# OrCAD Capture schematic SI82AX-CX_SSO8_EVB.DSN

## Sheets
1 PAGE3_Power_Connectors: size A; title: Power Connectors; rev: 1.0; note: SI82AX-CX_SSO8_EVB
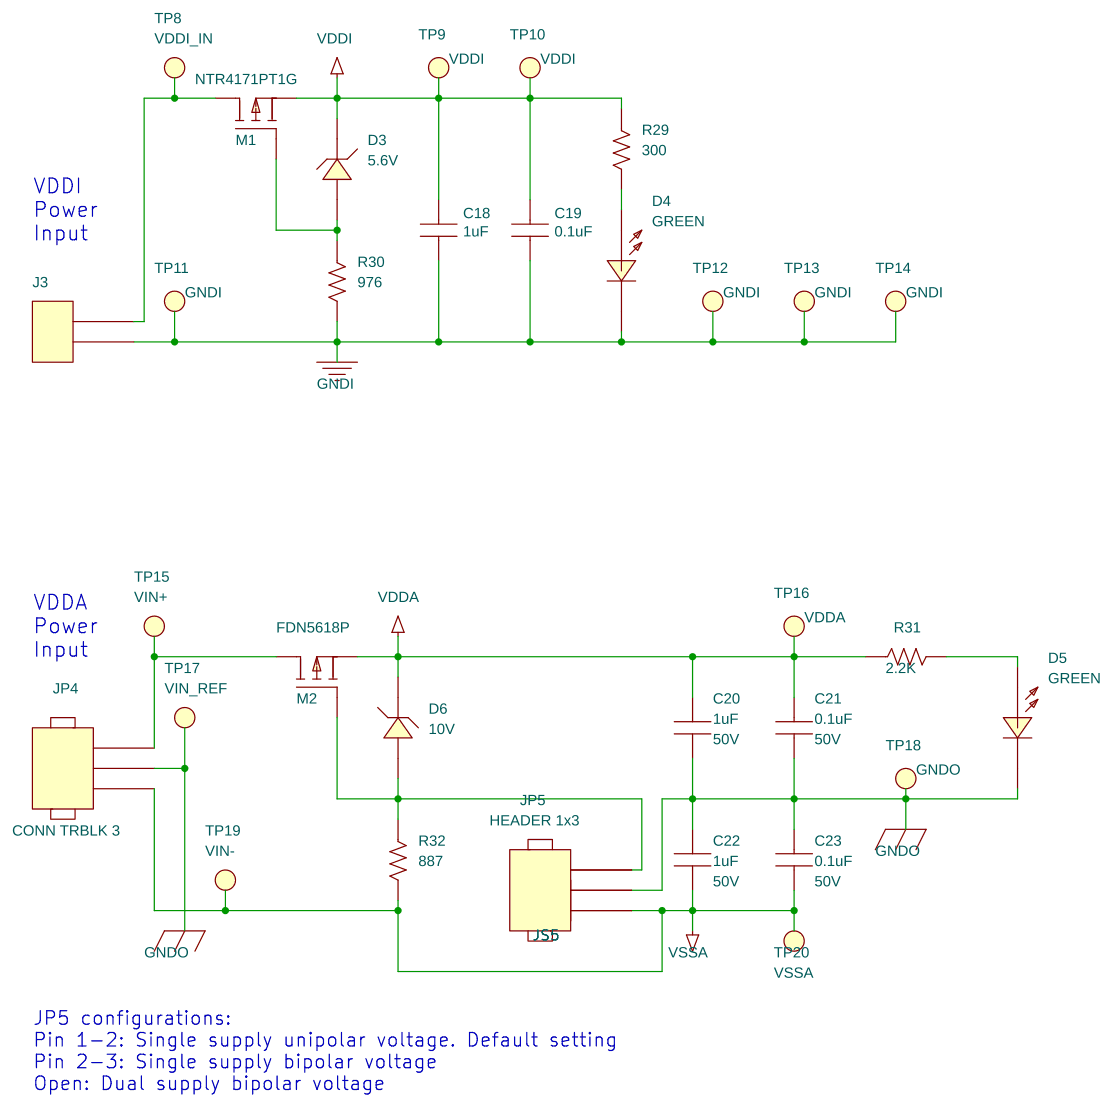
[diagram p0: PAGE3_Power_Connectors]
2 PAGE2_Mechanicals: size A; title: Mechanicals
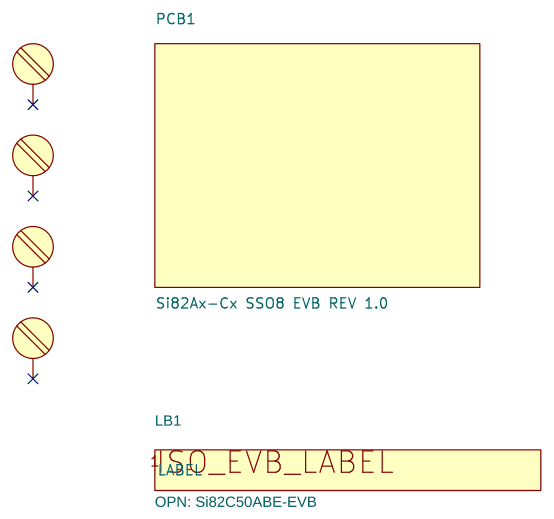
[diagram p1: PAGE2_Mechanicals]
3 PAGE1_Single_Driver: size B; title: Single Driver
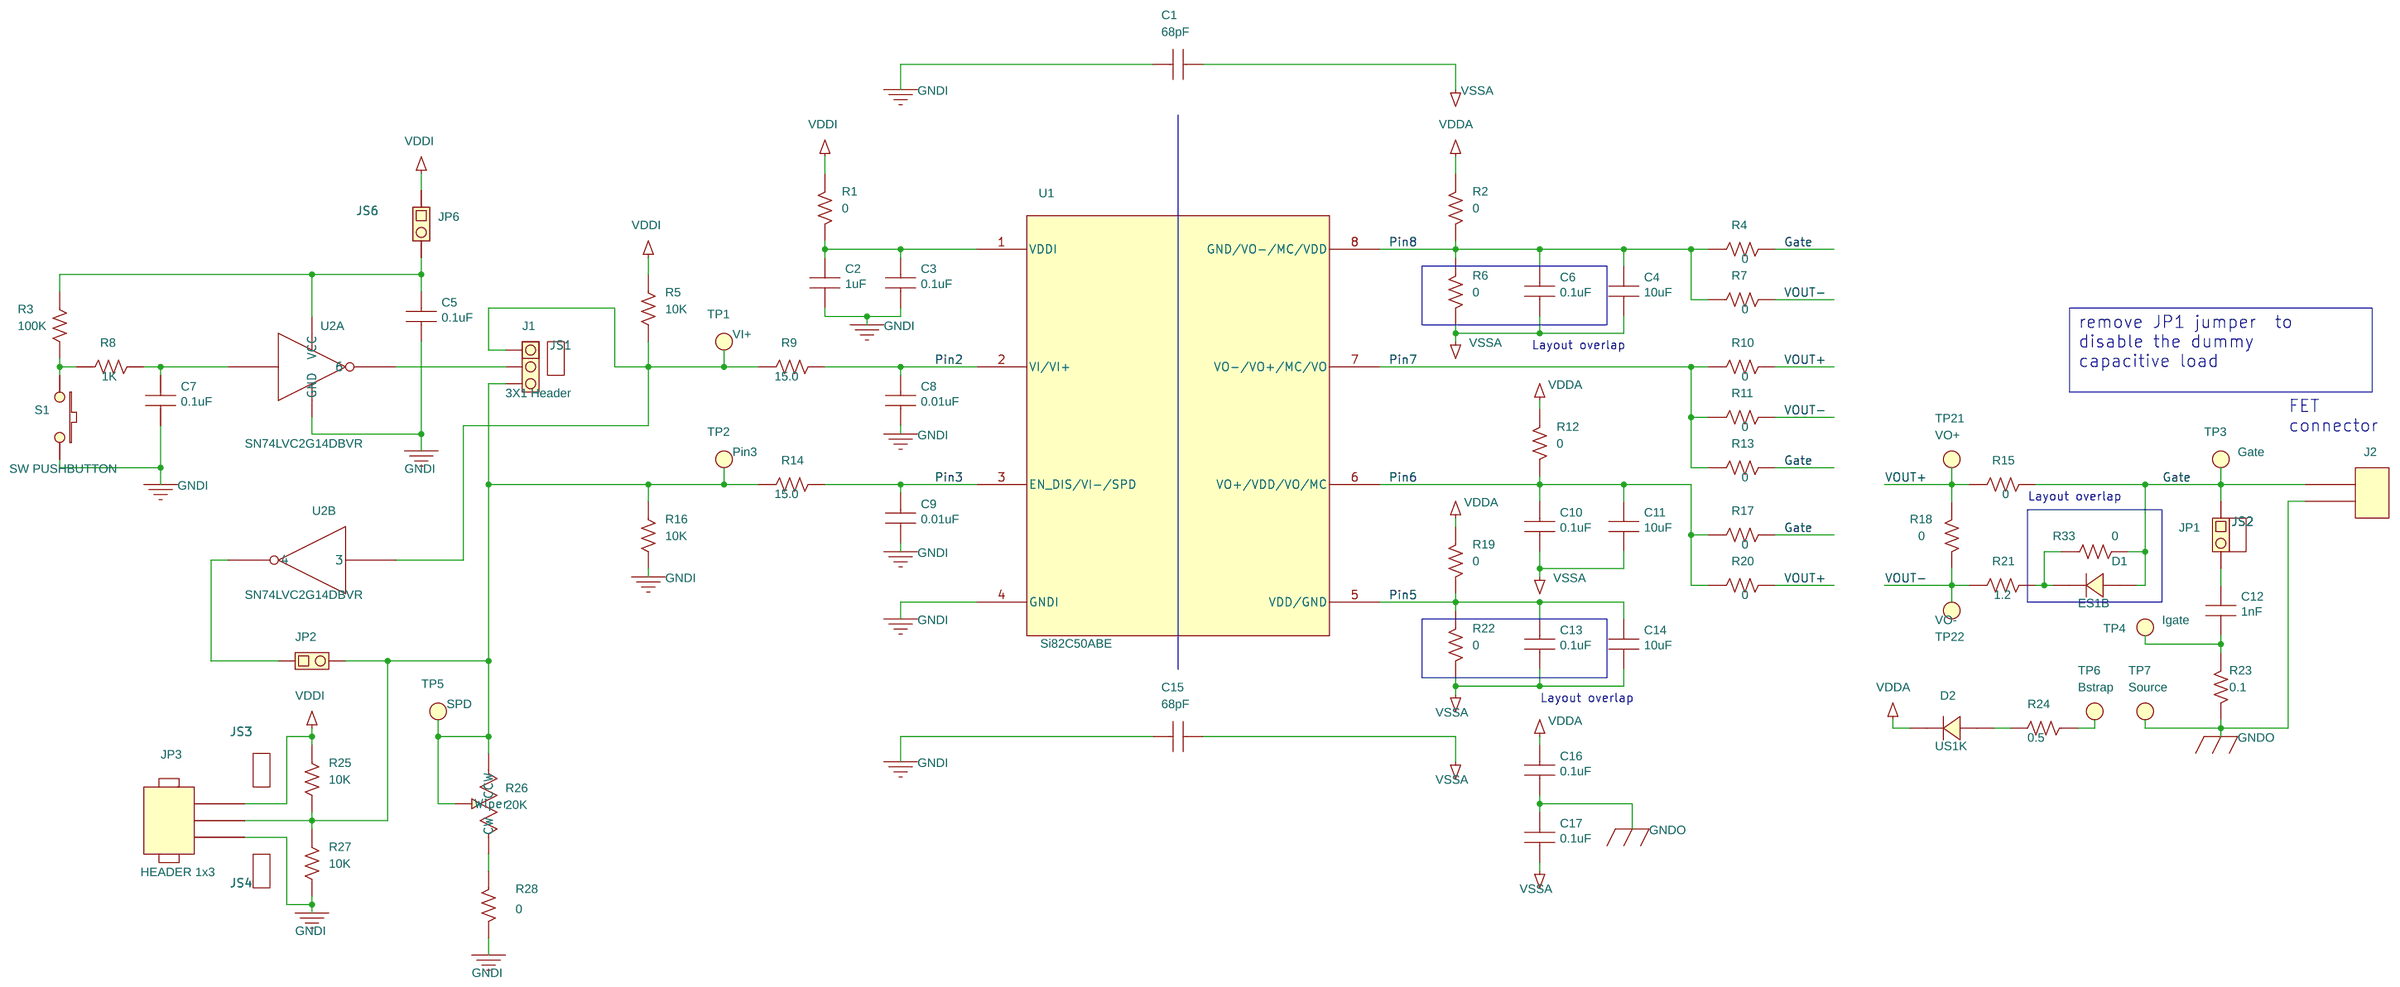
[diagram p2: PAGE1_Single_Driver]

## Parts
sheet PAGE1_Single_Driver
C1  68pF  [C1808]
C2  1uF  [C0603]
C3  0.1uF  [C0603]
C4  10uF  [C0805]
C5  0.1uF  [C0603]
C6  0.1uF  [C0603]
C7  0.1uF  [C0603]
C8  0.01uF  [C0402]
C9  0.01uF  [C0402]
C10  0.1uF  [C0603]
C11  10uF  [C0805]
C12  1nF  [C0805]
C13  0.1uF  [C0603]
C14  10uF  [C0805]
C15  68pF  [C1808]
C16  0.1uF  [C0603]
C17  0.1uF  [C0603]
D1  ES1B  [DO-214AC]
D2  US1K  [DO-214AC]
J1  3X1 Header  [CONN1X3-TSM]
J2  CONN TRBLK 2  [CON1X2-1725656]
JP1  HEADER 1X2  [CONN1X2]
JP2  HEADER 1X2  [CONN1X2]
JP3  HEADER 1x3  [CONN-1X3]
JP6  HEADER 1X2  [CONN1X2]
JS1  Jumper Shunt  [SHUNT]
JS2  Jumper Shunt  [SHUNT]
JS3  Jumper Shunt  [SHUNT]
JS4  Jumper Shunt  [SHUNT]
JS6  Jumper Shunt  [SHUNT]
R1  0  [R0603]
R2  0  [R0603]
R3  100K  [R0603]
R4  0  [R0805]
R5  10K  [R0603]
R6  0  [R0603]
R7  0  [R0805]
R8  1K  [R0603]
R9  15.0  [R0603]
R10  0  [R0805]
R11  0  [R0805]
R12  0  [R0603]
R13  0  [R0805]
R14  15.0  [R0603]
R15  0  [R0805]
R16  10K  [R0603]
R17  0  [R0805]
R18  0  [R0603]
R19  0  [R0603]
R20  0  [R0805]
R21  1.2  [R0805]
R22  0  [R0603]
R23  0.1  [R0603]
R24  0.5  [R0805]
R25  10K  [R0603]
R26  20K  [POT-PVG3A]
R27  10K  [R0603]
R28  0  [R0603]
R33  0  [R0805]
S1  SW PUSHBUTTON  [SW-PB-TL3302]
TP1  TESTPOINT  [TP_MINIATURE_SMT]
TP2  TESTPOINT  [TP_MINIATURE_SMT]
TP3  TESTPOINT  [TP_MINIATURE_SMT]
TP4  TESTPOINT  [TP_MINIATURE_SMT]
TP5  TESTPOINT  [TP_MINIATURE_SMT]
TP6  TESTPOINT  [TP_MINIATURE_SMT]
TP7  TESTPOINT  [TP_MINIATURE_SMT]
TP21  TESTPOINT  [TP_MINIATURE_SMT]
TP22  TESTPOINT  [TP_MINIATURE_SMT]
U1  Si82C50ABE  [SO8N11.5P1.27]
U2  SN74LVC2G14DBVR  [SOT6N2.8P0.95]  (sections A,B)
sheet PAGE2_Mechanicals
LB1  OPN: Si82C50ABE-EVB  [PTL-14-717]
MH1  SCREW/STANDOFF  [MH-125]
MH2  SCREW/STANDOFF  [MH-125]
MH3  SCREW/STANDOFF  [MH-125]
MH4  SCREW/STANDOFF  [MH-125]
PCB1  Si82Ax-Cx SSO8 EVB REV 1.0  [N/A]
sheet PAGE3_Power_Connectors
C18  1uF  [C0603]
C19  0.1uF  [C0402]
C20  1uF  [C0805]
C21  0.1uF  [C0603]
C22  1uF  [C0805]
C23  0.1uF  [C0603]
D3  5.6V  [SOD-123]
D4  GREEN  [LED-0603]
D5  GREEN  [LED-0603]
D6  10V  [SOD-123]
J3  CONN TRBLK 2  [CON1X2-1725656]
JP4  CONN TRBLK 3  [CON1X3-1725669]
JP5  HEADER 1x3  [CONN-1X3]
JS5  Jumper Shunt  [SHUNT]
M1  NTR4171PT1G  [SOT23-GSD]
M2  FDN5618P  [SOT23-GSD]
R29  300  [R0603]
R30  976  [R1206]
R31  2.2K  [R1206]
R32  887  [R2512]
TP8  RED  [TESTPOINT]
TP9  TESTPOINT  [TP_MINIATURE_SMT]
TP10  TESTPOINT  [TP_MINIATURE_SMT]
TP11  BLACK  [TESTPOINT]
TP12  TESTPOINT  [TP_MINIATURE_SMT]
TP13  TESTPOINT  [TP_MINIATURE_SMT]
TP14  TESTPOINT  [TP_MINIATURE_SMT]
TP15  RED  [TESTPOINT]
TP16  TESTPOINT  [TP_MINIATURE_SMT]
TP17  BLACK  [TESTPOINT]
TP18  TESTPOINT  [TP_MINIATURE_SMT]
TP19  WHITE  [TESTPOINT]
TP20  TESTPOINT  [TP_MINIATURE_SMT]

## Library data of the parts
C1 C15 = CAP_NP: CAP, 68pF, 250V, ±10%, Y2, 1808; Manufacturer: MuRata; ManufacturerPN: GA342D1XGF680JY02L; Rating: Y2; SiLabsPN: GA342D1XGF680JY02L; Tolerance: ±10%; Type: Y2; Voltage: 250V; Datasheet: muRata Safety Y1-3.pdf
C2 = CAP_NP: CAP, 1uF, 25V, ±10%, X7R, 0603; FPLIST: C0603,C0603L; Manufacturer: MuRata; ManufacturerPN: GCM188R71E105KA49; SiLabsPN: GCM188R71E105KA49; Tolerance: ±10%; Type: X7R; Voltage: 25V; Datasheet: GCM188R71E105KA49_EC-data.pdf
C3 C5 C7 = CAP_NP: CAP, 0.1uF, 25V, ±10%, X7R, 0603; Manufacturer: Venkel; ManufacturerPN: C0603X7R250-104K; SiLabsPN: C0603X7R250-104K; Tolerance: ±10%; Type: X7R; Voltage: 25V; Datasheet: PID_C.pdf
C4 C11 C14 = CAP_NP: CAP, 10uF, 50V, ±10%, X5R, 0805; Manufacturer: Murata; ManufacturerPN: GRM21BR61H106KE43L; SiLabsPN: C0805X5R500-106K; Tolerance: ±10%; Type: X5R; Voltage: 50V; Datasheet: GRM21BR61H106KE43-01A.pdf
C6 C10 C13 C16 C17 C21 C23 = CAP_NP: CAP, 0.1uF, 50V, ±10%, X7R, 0603; Manufacturer: Venkel; ManufacturerPN: C0603X7R500-104K; SiLabsPN: C0603X7R500-104K; Tolerance: ±10%; Type: X7R; Voltage: 50V; Datasheet: PID_C.pdf
C8 C9 = CAP_NP: CAP, 0.01uF, 25V, ±10%, X7R, 0402; Manufacturer: Venkel; ManufacturerPN: C0402X7R250-103K; SiLabsPN: C0402X7R250-103K; Tolerance: ±10%; Type: X7R; Voltage: 25V; Datasheet: PID_C.pdf
C12 = CAP_NP: CAP, 1nF, 50V, ±1%, C0G, 0805; Manufacturer: Venkel; ManufacturerPN: C0805C0G500-102F; SiLabsPN: C0805C0G500-102F; Tolerance: ±1%; Type: C0G; Voltage: 50V; Datasheet: PID_C.pdf
D1 = DIODE: DIO, FAST, 100V, 1.0A, SMA; Manufacturer: Diodes Inc.; Rating: 1.0A; Type: Fast; Voltage: 100V; Datasheet: ds14001.pdf
D2 = DIODE: DIO, SWITCH, ULTRA FAST, 800V, 1.0A, SMA; Manufacturer: Diodes Inc.; ManufacturerPN: US1K-13-F; Rating: 1.0A; SiLabsPN: US1K-13-F; Type: Switch, Ultra Fast; Voltage: 800V; Datasheet: ds16008.pdf
J1 = BRCM-HDR1X3: Header, 3x1, 0.1in pitch, 10u Au Plated, SMD; Manufacturer: Samtec; ManufacturerPN: TSM-103-01-L-SV; SiLabsPN: TSM-103-01-L-SV; Type: Header; Datasheet: TSM.PDF
J2 J3 = CONN_TRBLK_2: CONN, TERM BLOCK 2POS, 2.54MM, RT PCB; Manufacturer: PHOENIX CONTACT; ManufacturerPN: 1725656; SiLabsPN: 1725656; Type: TERM BLK; Datasheet: 1725656.pdf
JP1 JP2 JP6 = JUMPER: Header, 2x1, 0.1in pitch, Tin Plated; Manufacturer: Samtec; ManufacturerPN: TSW-102-07-T-S; SiLabsPN: TSW-102-07-T-S; Type: Header; Datasheet: TSW_TH.pdf
JP3 JP5 = CONN_HEADER_3: Header, 3x1, 0.1in pitch, Tin Plated; Manufacturer: Samtec; ManufacturerPN: TSW-103-07-T-S; SiLabsPN: TSW-103-07-T-S; Type: Header; Datasheet: TSW_TH.PDF
JS1-JS6 = JMPR_SHUNT1: Shunt, 1x2, 0.1in pitch, Tin plating; Manufacturer: Samtec; ManufacturerPN: SNT-100-BK-T; SiLabsPN: SNT-100-BK-T; Type: Shunt; Datasheet: SNT.pdf
R1 R2 R6 R12 R18 R19 R22 R28 = RES: RES, 0 Ohm, 1A, ThickFilm, 0603; FPLIST: R0603,R0603L; Manufacturer: Venkel; ManufacturerPN: CR0603-16W-000; Rating: 1A; SiLabsPN: CR0603-16W-000; Type: ThickFilm; Datasheet: PID_CR.pdf
R3 = RES: RES, 100K, 1/10W, ±5%, ThickFilm, 0603; Manufacturer: Venkel; ManufacturerPN: CR0603-10W-104J; Rating: 1/10W; SiLabsPN: CR0603-10W-104J; Tolerance: ±5%; Type: ThickFilm; Datasheet: PID_CR.pdf
R4 R7 R10 R11 R13 R15 R17 R20 R33 = RES: RES, 0 Ohm, 2A, ThickFilm, 0805; Manufacturer: Venkel; ManufacturerPN: CR0805-10W-000; Rating: 2A; SiLabsPN: CR0805-10W-000; Type: ThickFilm; Datasheet: PID_CR.pdf
R5 R16 R25 R27 = RES: RES, 10K, 1/16W, ±1%, ThickFilm, 0603; Manufacturer: Venkel; ManufacturerPN: CR0603-16W-1002F; Rating: 1/16W; SiLabsPN: CR0603-16W-1002F; Tolerance: ±1%; Type: ThickFilm; Datasheet: PID_CR.pdf
R8 = RES: RES, 1K, 1/10W, ±5%, ThickFilm, 0603; Manufacturer: Venkel; ManufacturerPN: CR0603-10W-1001J; Rating: 1/10W; SiLabsPN: CR0603-10W-1001J; Tolerance: ±5%; Type: ThickFilm; Datasheet: PID_CR.pdf
R9 R14 = RES: RES, 15.0 Ohm, 1/16W, ±1%, ThickFilm, 0603; Manufacturer: Venkel; ManufacturerPN: CR0603-16W-15R0F; Rating: 1/16W; SiLabsPN: CR0603-16W-15R0F; Tolerance: ±1%; Type: ThickFilm; Datasheet: PID_CR.pdf
R21 = RES: RES, 1.2 Ohm, 1/10W, ±5%, ThickFilm, 0805; Manufacturer: Venkel; ManufacturerPN: CR0805-10W-1R2J; Rating: 1/10W; SiLabsPN: CR0805-10W-1R2J; Tolerance: ±5%; Type: ThickFilm; Datasheet: PID_CR.pdf
R23 = RES: RES, 0.1 Ohm, 1/8W, ±1%, ThickFilm, 0603; Manufacturer: Venkel; ManufacturerPN: LCR0603-R100F; Rating: 1/8W; SiLabsPN: CR0603-8W-R100F; Tolerance: ±1%; Type: ThickFilm; Datasheet: PID_CR.pdf
R24 = RES: RES, 0.5 Ohm, 1/4W, ±1%, ThickFilm, 0805; Manufacturer: Venkel; ManufacturerPN: LCR0805-R500F; Rating: 1/4W; SiLabsPN: LCR0805-R500F; Tolerance: ±1%; Type: ThickFilm; Voltage: 500V; Datasheet: PID_CR.pdf
R26 = POT: TRIMPOT, 20K, 1T, TOP ADJ, Sealed, 3mm, PVG3 Series, SMD; Manufacturer: MuRata; ManufacturerPN: PVG3A203C01R00; Rating: 1/4W; SiLabsPN: PVG3A203C01R00; Tolerance: 20%; Type: TRIM; Datasheet: PVG3 Series.pdf
S1 = SW-PB-SPST-SHORT: SWITCH, MOM, PB, TACTILE, NO, 70C, 3.5x6mm, SMD; Manufacturer: E-SWITCH; ManufacturerPN: TL3302AF180QJ; Rating: 50mA; SiLabsPN: TL3302AF180QJ; Type: Tactile; Voltage: 12VDC; Datasheet: TL3302-346326.pdf
TP1 = TEST_POINT: TESTPOINT, MINIATURE, SMD; Manufacturer: Keystone; ManufacturerPN: 5019; SiLabsPN: 5019; Silk: VI+; Datasheet: 5019.pdf
TP2 = TEST_POINT: TESTPOINT, MINIATURE, SMD; Manufacturer: Keystone; ManufacturerPN: 5019; SiLabsPN: 5019; Silk: Pin3; Datasheet: 5019.pdf
TP3 = TEST_POINT: TESTPOINT, MINIATURE, SMD; Manufacturer: Keystone; ManufacturerPN: 5019; SiLabsPN: 5019; Silk: Gate; Datasheet: 5019.pdf
TP4 = TEST_POINT: TESTPOINT, MINIATURE, SMD; Manufacturer: Keystone; ManufacturerPN: 5019; SiLabsPN: 5019; Silk: Igate; Datasheet: 5019.pdf
TP5 = TEST_POINT: TESTPOINT, MINIATURE, SMD; Manufacturer: Keystone; ManufacturerPN: 5019; SiLabsPN: 5019; Silk: SPD; Datasheet: 5019.pdf
TP6 = TEST_POINT: TESTPOINT, MINIATURE, SMD; Manufacturer: Keystone; ManufacturerPN: 5019; SiLabsPN: 5019; Silk: Bstrap; Datasheet: 5019.pdf
TP7 = TEST_POINT: TESTPOINT, MINIATURE, SMD; Manufacturer: Keystone; ManufacturerPN: 5019; SiLabsPN: 5019; Silk: Source; Datasheet: 5019.pdf
TP21 = TEST_POINT: TESTPOINT, MINIATURE, SMD; Manufacturer: Keystone; ManufacturerPN: 5019; SiLabsPN: 5019; Silk: VO+; Datasheet: 5019.pdf
TP22 = TEST_POINT: TESTPOINT, MINIATURE, SMD; Manufacturer: Keystone; ManufacturerPN: 5019; SiLabsPN: 5019; Silk: VO-; Datasheet: 5019.pdf
U1 = Si82AxBxCx_SSO8_Common: IC, ISOdriver, Performance Driver, 8V UVLO, 6KV, SO8WB; Manufacturer: Skyworks; ManufacturerPN: Si82C50ABE-IS4; Rating: 6000 VRMS; SiLabsPN: Si82C50ABE-IS4; Type: ISOdriver; Voltage: 30V; Datasheet: POD-003791_PACKAGE_OUTLINE_SOIC_8L_WB_RevA.pdf
U2 = SN74LVC2G14DBVR: IC, INVERTER DUAL SHMT-T SOT-23-6; Manufacturer: TI; ManufacturerPN: SN74LVC2G14DBV; SiLabsPN: SN74LVC2G14DBV; Type: Inverter; Voltage: 5V; Datasheet: SN74LVC2G14.pdf
LB1 = ISO_EVB_Label: LABEL, PDB, POLYIMIDE, WHITE, 1.00 in. X 0.187 in., FONT 2; Manufacturer: Skyworks; ManufacturerPN: LABEL-Si82C50ABE-EVB; SiLabsPN: LABEL-Si82C50ABE-EVB; Type: POLYIMIDE, WHITE; Datasheet: Brady TLS2200 Label PTL-14-717.pdf
MH1-MH4 = #4_PTH_SCREW-STANDOFF: SCREW/STANDOFF, 4-40X1/4" NYL, 4-40X1/4"X1" NYL, PTH; Manufacturer: VARIOUS; ManufacturerPN: NSS-4-4-01/2401; SiLabsPN: NSS-4-4-01/2401; Type: HDW; Datasheet: RichcoPlasticCo_Screws - SPC_Technology_spacers.pdf
PCB1 = PCB: PCB, BARE BOARD, Si82Ax-Cx SSO8 EVB REV 1.0; Manufacturer: Skyworks; Type: BARE PCB
C18 = CAP_NP: CAP, 1uF, 10V, ±10%, X7R, 0603; Manufacturer: Venkel; ManufacturerPN: C0603X7R100-105K; SiLabsPN: C0603X7R100-105K; Tolerance: ±10%; Type: X7R; Voltage: 10V; Datasheet: PID_C.pdf
C19 = CAP_NP: CAP, 0.1uF, 10V, ±10%, X7R, 0402; FPLIST: C0402,C0402L; Manufacturer: Venkel; ManufacturerPN: C0402X7R100-104K; SiLabsPN: C0402X7R100-104K; Tolerance: ±10%; Type: X7R; Voltage: 10V; Datasheet: PID_C.pdf
C20 C22 = CAP_NP: CAP, 1uF, 50V, ±10%, X7R, 0805; Manufacturer: Samsung; ManufacturerPN: CL21B105KBFNNNE; SiLabsPN: C0805X7R500-105K; Tolerance: ±10%; Type: X7R; Voltage: 50V; Datasheet: CL21B105KBFNNNE.pdf
D3 = DIODE_ZENER: DIO, ZENER, 5.6V, 500mW, SOD123; Manufacturer: On Semi; ManufacturerPN: SZMMSZ5232BT1G; Rating: 500mW; SiLabsPN: SZMMSZ5232BT1G; Tolerance: 5%; Type: Zener; Datasheet: MMSZ5221BT1-D.pdf
D4 D5 = LED: LED, GREEN, 528nM, 5mA, 2.8V, 154mcd, 0603; Manufacturer: LITE-ON TECHNOLOGY CORP; ManufacturerPN: LTST-C193TGKT-5A; Rating: 20mA; SiLabsPN: LTST-C193TGKT-5A; Datasheet: LTST-C193TGKT-5A.pdf
D6 = DIODE_ZENER: DIO, ZENER, 10V, 500mW, SOD123; Manufacturer: On Semi; ManufacturerPN: MMSZ4697T1G; Rating: 500mW; SiLabsPN: MMSZ4697T1G; Tolerance: 5%; Type: Zener; Datasheet: MMSZ4678T1-D.pdf
JP4 = CONN_HEADER_3: CONN, TERM BLOCK 3POS, 2.54MM, RT PCB; Manufacturer: PHOENIX CONTACT; ManufacturerPN: 1725669; SiLabsPN: 1725669; Type: TERM BLK; Datasheet: 1725669.pdf
M1 = PFET_3PIN: TRANSISTOR, MOSFET, P-CHNL, -30V, -3.5A, SOT23; Manufacturer: ON Semiconductor; Rating: -3.5A; Type: P-CHNL; Voltage: -30V; Datasheet: NTR4171P-D.PDF
M2 = PFET_3PIN: TRANSISTOR, MOSFET, P-CHNL, 60V, 1.25A, 0.3 Ohms, SOT23; Manufacturer: Fairchild; Rating: 1.25A; Type: P-CHNL; Voltage: 60V; Datasheet: FDN5618P.PDF
R29 = RES: RES, 300 Ohm, 1/16W, ±5%, ThickFilm, 0603; FPLIST: R0603,R0603L; Manufacturer: Venkel; ManufacturerPN: CR0603-16W-301J; Rating: 1/16W; SiLabsPN: CR0603-16W-301J; Tolerance: ±5%; Type: ThickFilm; Datasheet: PID_CR.pdf
R30 = RES: RES, 976 Ohm, 1/4W, ±1%, ThickFilm, 1206; Manufacturer: Venkel; ManufacturerPN: CR1206-4W-9760F; Rating: 1/4W; SiLabsPN: CR1206-4W-9760F; Tolerance: ±1%; Type: ThickFilm; Datasheet: PID_CR.pdf
R31 = RES: RES, 2.2K, 1/4W, ±5%, ThickFilm, 1206; Manufacturer: Venkel; ManufacturerPN: CR1206-4W-222JT; Rating: 1/4W; SiLabsPN: CR1206-4W-222J; Tolerance: ±5%; Type: ThickFilm; Datasheet: PID_CR.pdf
R32 = RES: RES, 887 Ohm, 1W, ±1%, ThickFilm, 2512; Manufacturer: Panasonic Electronic Components; ManufacturerPN: ERJ-1TNF8870U; Rating: 1W; SiLabsPN: CR2512-1W-8870F; Tolerance: ±1%; Type: ThickFilm; Datasheet: AOA0000C304.pdf
TP8 = TEST_POINT: TESTPOINT, RED, PTH; Manufacturer: Kobiconn; ManufacturerPN: 151-207-RC; SiLabsPN: 151-207; Silk: VDDI_IN; Type: Loop; Datasheet: KC-300780.pdf
TP9 TP10 = TEST_POINT: TESTPOINT, MINIATURE, SMD; Manufacturer: Keystone; ManufacturerPN: 5019; SiLabsPN: 5019; Silk: VDDI; Datasheet: 5019.pdf
TP11 = TEST_POINT: TESTPOINT, BLACK, PTH; Manufacturer: Kobiconn; ManufacturerPN: 151-203-RC; SiLabsPN: 151-203; Silk: GNDI; Type: Loop; Datasheet: KC-300780.pdf
TP12-TP14 = TEST_POINT: TESTPOINT, MINIATURE, SMD; Manufacturer: Keystone; ManufacturerPN: 5019; SiLabsPN: 5019; Silk: GNDI; Datasheet: 5019.pdf
TP15 = TEST_POINT: TESTPOINT, RED, PTH; Manufacturer: Kobiconn; ManufacturerPN: 151-207-RC; SiLabsPN: 151-207; Silk: VIN+; Type: Loop; Datasheet: KC-300780.pdf
TP16 = TEST_POINT: TESTPOINT, MINIATURE, SMD; Manufacturer: Keystone; ManufacturerPN: 5019; SiLabsPN: 5019; Silk: VDDA; Datasheet: 5019.pdf
TP17 = TEST_POINT: TESTPOINT, BLACK, PTH; Manufacturer: Kobiconn; ManufacturerPN: 151-203-RC; SiLabsPN: 151-203; Silk: VIN_REF; Type: Loop; Datasheet: KC-300780.pdf
TP18 = TEST_POINT: TESTPOINT, MINIATURE, SMD; Manufacturer: Keystone; ManufacturerPN: 5019; SiLabsPN: 5019; Silk: GNDO; Datasheet: 5019.pdf
TP19 = TEST_POINT: TESTPOINT, WHITE, PTH; Manufacturer: Kobiconn; ManufacturerPN: 151-201-RC; SiLabsPN: 151-201; Silk: VIN-; Type: Loop; Datasheet: KC-300780.pdf
TP20 = TEST_POINT: TESTPOINT, MINIATURE, SMD; Manufacturer: Keystone; ManufacturerPN: 5019; SiLabsPN: 5019; Silk: VSSA; Datasheet: 5019.pdf

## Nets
GNDI: C1.1 C2.2 C3.2 C5.2 C7.2 C8.2 C9.2 C15.1 C18.2 C19.2 D4.K(CATHODE) J3.2 JP3.3 R16.2 R27.2 R28.2 R30.2 S1.2 TP11.1(Point) TP12.1(Point) TP13.1(Point) TP14.1(Point) U1.4(GNDI) U2.2(GND)
GNDO: C16.2 C17.1 C20.2 C21.2 C22.1 C23.1 D5.K(CATHODE) J2.1 JP4.2 JP5.2 R23.2 TP7.1(Point) TP17.1(Point) TP18.1(Point)
VDDA: C16.1 C20.1 C21.1 D2.K(CATHODE) D6.K(CATHODE) M2.S(SOURCE) R2.1 R12.1 R19.1 R31.1 TP16.1(Point)
VDDI: C18.1 C19.1 D3.K(CATHODE) JP3.1 JP6.1 M1.S(SOURCE) R1.1 R5.1 R25.1 R29.1 TP9.1(Point) TP10.1(Point)
VSSA: C1.2 C4.2 C6.2 C10.2 C11.2 C13.2 C14.2 C15.2 C17.2 C22.2 C23.2 JP4.3 JP5.1 R6.2 R22.2 R32.2 TP19.1(Point) TP20.1(Point)
Gate: D1.A(ANODE) J2.2 JP1.1 R4.2 R13.2 R15.2 R17.2 R33.2 TP3.1(Point)
LABEL: LB1.1(LABEL)
Pin2: C8.1 R9.2 U1.2(VI/VI+)
Pin3: C9.1 R14.2 U1.3(EN_DIS/VI-/SPD)
Pin5: C13.1 C14.1 R19.2 R22.1 U1.5(VDD/GND)
Pin6: C10.1 C11.1 R12.2 R17.1 R20.1 U1.6(VO+/VDD/VO/MC)
Pin7: R10.1 R11.1 R13.1 U1.7(VO-/VO+/MC/VO)
Pin8: C4.1 C6.1 R2.2 R4.1 R6.1 R7.1 U1.8(GND/VO-/MC/VDD)
VOUT+: R10.2 R15.1 R18.1 R20.2 TP21.1(Point)
VOUT-: R7.2 R11.2 R18.2 R21.1 TP22.1(Point)
N16361749: D3.A(ANODE) M1.G(GATE) R30.1
N16362266: J3.1 M1.D(DRAIN) TP8.1(Point)
N16362479: D4.A(ANODE) R29.2
N16363374: D6.A(ANODE) JP5.3 M2.G(GATE) R32.1
N16363786: JP4.1 M2.D(DRAIN) TP15.1(Point)
N16364430: D5.A(ANODE) R31.2
N16365952: C2.1 C3.1 R1.2 U1.1(VDDI)
N16366694: J1.3 JP2.2 JP3.2 R14.1 R16.1 R25.2 R26.1(CCW) R26.2(Wiper) R27.1 TP2.1(Point) TP5.1(Point)
N16367392: R26.3(CW) R28.1
N16368114: C5.1 JP6.2 R3.1 U2.5(VCC)
N16368658: C7.1 R8.2 U2.1
N16368673: R3.2 R8.1 S1.1
N16368830: J1.2 U2.6
N16369034: J1.1 R5.2 R9.1 TP1.1(Point) U2.3
N16371598: D1.K(CATHODE) R21.2 R33.1
N16372242: C12.1 JP1.2
N16372246: C12.2 R23.1 TP4.1(Point)
N16378592: JP2.1 U2.4
N16380141: R24.1 TP6.1(Point)
N16380165: D2.A(ANODE) R24.2

Not connected (* = marked no-connect by the designer): MH1 1(MH)*; MH2 1(MH)*; MH3 1(MH)*; MH4 1(MH)*

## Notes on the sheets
sheet 1
- VDDI
  Power
  Input
- VDDA
  Power
  Input
- JP5 configurations:
  Pin 1-2: Single supply unipolar voltage. Default setting
  Pin 2-3: Single supply bipolar voltage
  Open: Dual supply bipolar voltage
sheet 3
- remove JP1 jumper  to
  disable the dummy
  capacitive load
- Layout overlap
- FET
  connector
- Layout overlap
- Layout overlap
